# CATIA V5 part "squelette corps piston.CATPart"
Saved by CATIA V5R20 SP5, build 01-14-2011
Part number: squelette corps piston
Bounding box of the stored display mesh (mm): x 523.543 to 9574.399, y -10000 to 10000, z 7371.579 to 10647.541
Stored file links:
  M:\EU_thinkMotion\IAO_2010\iao\IAO_MMS_Groupe1\Problemes\gduval\Gduval\train d'aterrissage squelette + piece kinematic\squelette corps piston.CATPart
  M:\EU_thinkMotion\IAO_2010\iao\IAO_MMS_Groupe1\Problemes\gduval\Gduval\train d'aterrissage squelette + piece kinematic\train d'aterrissage.CATProduct
  M:\EU_thinkMotion\IAO_2010\iao\IAO_MMS_Groupe1\Problemes\gduval\Gduval\train d'aterrissage squelette + piece kinematic\squelette de base.CATPart
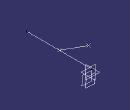
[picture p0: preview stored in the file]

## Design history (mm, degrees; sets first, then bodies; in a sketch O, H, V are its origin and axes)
External parameters (linked from other documents)
  `External.epaisseur bielle` = 500 mm
  `External.diamètre piston` = 835 mm
Set1
  Point1: linked copy from another document
  Point2: linked copy from another document
  Plane1: linked copy from another document
Body1 (main body)
  Line1: type PtPt, FirstPoint Point1, SecondPoint Point2
  Line2: type Normal, RefPoint Point1, RefSkin Plane1, Start 10000, End -10000
  Plane2: type Offset, RefPlane Plane1, Offset 1117.5 {= (`External.epaisseur bielle` +`External.diamètre piston` /2+200mm)}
